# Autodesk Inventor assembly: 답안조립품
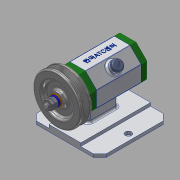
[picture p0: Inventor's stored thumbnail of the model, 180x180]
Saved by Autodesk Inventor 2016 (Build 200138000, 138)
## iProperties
Created: 2018-06
Part Number: 답안조립품
Material: 일반
Document SubType Name: Assembly
Designer: 605-15
Author: 605-15
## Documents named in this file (16)
- C:\Users\605-15\Desktop\480607V1021\답안조립품.iam
- C:\Users\605-15\Desktop\480607V1021\본체.ipt
- C:\Users\605-15\Desktop\480607V1021\베어링 15x32x9.ipt
- C:\Users\605-15\Desktop\480607V1021\앞커버.ipt
- C:\Users\605-15\Desktop\480607V1021\뒤커버.ipt
- C:\Users\605-15\Desktop\480607V1021\볼트 M4x12.ipt
- C:\Users\605-15\Desktop\480607V1021\오일 실 15 25 7.ipt
- C:\Users\605-15\Desktop\480607V1021\축.ipt
- C:\Users\605-15\Desktop\480607V1021\키 3x3x12.ipt
- 키 3x3x12.ipt
- C:\Users\605-15\Desktop\480607V1021\V벨트풀리.ipt
- C:\Users\605-15\Desktop\480607V1021\와셔 8x17.ipt
- C:\Users\605-15\Desktop\480607V1021\스프링와셔 8.ipt
- C:\Users\605-15\Desktop\480607V1021\너트 M8.ipt
- 너트 M8.ipt
- C:\Users\605-15\Desktop\480607V1021\고무캡.ipt
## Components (2 placed, 2 different names)
1. V벨트풀리:1 — 각도:2
2. 고무캡:1
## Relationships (1: Angle 1)
- 각도:2 [Angle]: V벨트풀리:1
